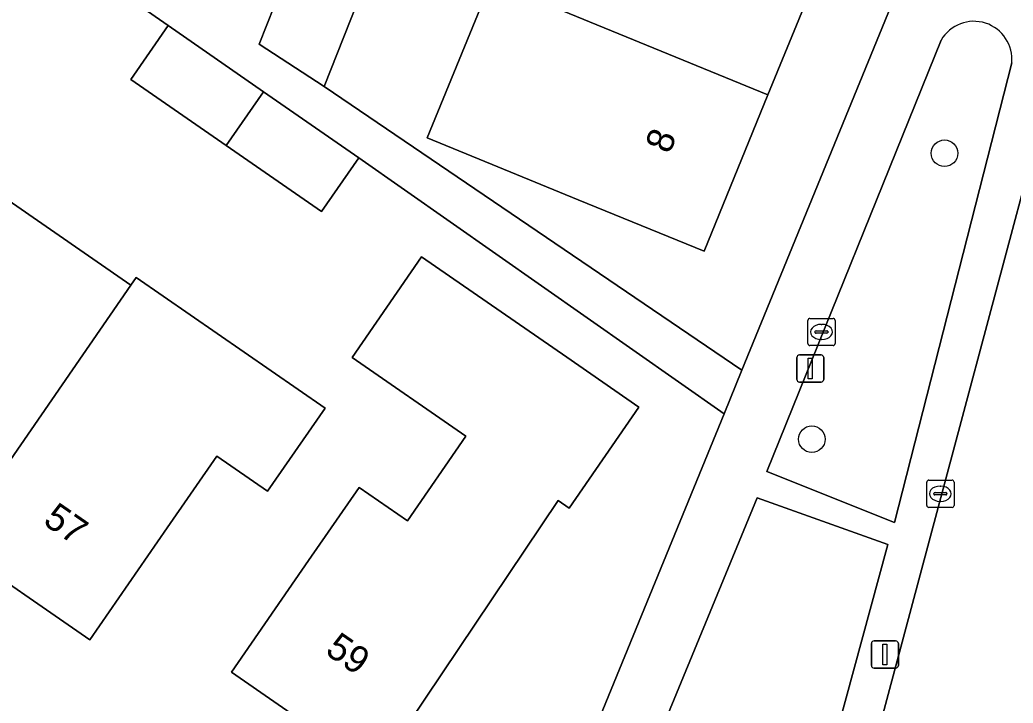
# Model space of a CAD drawing. Extents: x 162803 to 163818, y 381639 to 382475.
# Drawn here: x 163298.83 to 163335.38, y 381902.11 to 381927.23 of the extents above; entities that cross this region are included whole.
import ezdxf

# ---------------------------------------------------------------- set-up
doc = ezdxf.new("R2010")
doc.units = 0
for name, color, linetype in [('IMGEO_Boom', 7, 'Continuous'), ('IMGEO_Erf', 7, 'Continuous'), ('IMGEO_Groenvoorziening', 7, 'Continuous'), ('IMGEO_Kolk', 7, 'Continuous'), ('IMGEO_Lichtmast', 7, 'Continuous'), ('IMGEO_Pand', 7, 'Continuous'), ('IMGEO_Pand_nummerreeks', 7, 'Continuous'), ('IMGEO_Rijbaan_lokaal_open', 7, 'Continuous'), ('IMGEO_Voetpad_open', 7, 'Continuous')]:
    doc.layers.add(name, color=color, linetype=linetype)

msp = doc.modelspace()

# ---------------------------------------------------------------- linework, layer by layer
at = {"layer": 'IMGEO_Boom'}
for centre in [(163332.858, 381922.325), (163327.972, 381911.812)]:
    msp.add_circle(centre, 0.489, dxfattribs=at)
at = {"layer": 'IMGEO_Erf'}
for points in [[(163337.762, 381940.645), (163309.811, 381952.487), (163309.024, 381950.542), (163314.886, 381948.141), (163313.334, 381944.351), (163312.088, 381941.309), (163310.843, 381938.267), (163309.598, 381935.225), (163308.358, 381932.197), (163309.738, 381931.65), (163311.106, 381935.117), (163313.706, 381934.091), (163312.199, 381930.271), (163310.033, 381924.777), (163325.4, 381914.344), (163332.221, 381930.991), (163335.518, 381932.057)], [(163323.368, 381938.801), (163325.723, 381944.553), (163328.684, 381943.341), (163333.311, 381941.446), (163330.956, 381935.694), (163328.658, 381930.083), (163326.361, 381924.472), (163324.007, 381918.723), (163319.38, 381920.618), (163316.419, 381921.83), (163313.815, 381922.896), (163316.169, 381928.645), (163318.773, 381927.579), (163321.07, 381933.19)], [(163306.42, 381922.605), (163302.91, 381925.033), (163304.283, 381927.018), (163296.762, 381932.249), (163296.673, 381932.282), (163291.676, 381934.146), (163284.175, 381936.467), (163283.558, 381934.136), (163279.55, 381935.197), (163275.54, 381936.258), (163276.157, 381938.589), (163265.939, 381941.198), (163262.719, 381928.933), (163262.737, 381927.272), (163262.993, 381926.715), (163263.886, 381925.565), (163279.163, 381915.031), (163284.116, 381911.615), (163313.54, 381891.287), (163316.437, 381892.468), (163324.747, 381912.749), (163311.302, 381922.163), (163309.929, 381920.178)], [(163311.057, 381914.819), (163313.615, 381918.52), (163318.955, 381914.83), (163321.613, 381912.993), (163319.046, 381909.279), (163318.645, 381909.556), (163311.926, 381899.566), (163306.613, 381903.239), (163309.457, 381907.353), (163311.314, 381910.04), (163313.092, 381908.811), (163315.245, 381911.924)]]:
    msp.add_lwpolyline(points, close=True, dxfattribs=at)
msp.add_lwpolyline([(163295.64, 381927.812), (163292.797, 381923.7), (163291.24, 381921.447), (163296.05, 381918.122), (163296.477, 381917.827), (163298.397, 381920.603), (163302.92, 381917.476), (163303.116, 381917.759), (163310.061, 381912.957), (163307.945, 381909.897), (163306.077, 381911.189), (163304.25, 381908.546), (163301.406, 381904.433), (163296.331, 381907.941), (163291.38, 381911.364), (163286.305, 381914.872), (163289.794, 381919.919), (163287.322, 381921.628), (163284.851, 381923.335), (163281.365, 381918.292), (163276.283, 381921.805), (163271.323, 381925.235), (163266.238, 381928.75)], dxfattribs=at)
at = {"layer": 'IMGEO_Groenvoorziening'}
for points in [[(163332.732, 381926.487), (163326.319, 381910.623), (163331.019, 381908.748), (163335.33, 381925.646)], [(163330.776, 381907.94), (163325.963, 381909.657), (163320.28, 381895.893), (163318.976, 381892.714)], [(163325.799, 381889.715), (163326.399, 381891.882), (163330.776, 381907.94)]]:
    msp.add_lwpolyline(points, dxfattribs=at)
msp.add_arc((163333.938, 381925.779), 1.398, 354.5574, 149.568, dxfattribs=at)
at = {"layer": 'IMGEO_Kolk'}
for p, q in [((163327.904, 381916.254), (163328.756, 381916.254)), ((163327.829, 381915.328), (163327.829, 381916.18)), ((163328.317, 381916.034), (163328.342, 381916.034)), ((163328.83, 381916.18), (163328.83, 381915.328)), ((163328.088, 381915.748), (163328.088, 381915.76)), ((163328.526, 381915.711), (163328.128, 381915.711)), ((163328.131, 381915.797), (163328.529, 381915.797)), ((163328.572, 381915.76), (163328.572, 381915.748)), ((163328.756, 381915.254), (163327.904, 381915.254)), ((163328.34, 381915.474), (163328.315, 381915.474)), ((163332.205, 381909.379), (163332.205, 381910.231)), ((163332.28, 381910.305), (163333.132, 381910.305)), ((163332.693, 381910.085), (163332.718, 381910.085)), ((163333.206, 381910.231), (163333.206, 381909.379)), ((163332.464, 381909.799), (163332.464, 381909.811)), ((163332.902, 381909.762), (163332.504, 381909.762)), ((163332.507, 381909.848), (163332.905, 381909.848)), ((163332.948, 381909.811), (163332.948, 381909.799)), ((163332.716, 381909.525), (163332.691, 381909.525)), ((163333.132, 381909.305), (163332.28, 381909.305))]:
    msp.add_line(p, q, dxfattribs=at)
for points in [[(163327.904, 381916.254), (163328.756, 381916.254)], [(163327.829, 381915.328), (163327.829, 381916.18)], [(163328.83, 381916.18), (163328.83, 381915.328)], [(163328.756, 381915.254), (163327.904, 381915.254)], [(163332.205, 381909.379), (163332.205, 381910.231)], [(163332.28, 381910.305), (163333.132, 381910.305)], [(163333.206, 381910.231), (163333.206, 381909.379)], [(163333.132, 381909.305), (163332.28, 381909.305)]]:
    msp.add_lwpolyline(points, dxfattribs=at)
for centre, radius, start, end in [((163327.906, 381916.178), 0.0765, 91.552, 178.448), ((163327.906, 381916.178), 0.0765, 91.552, 178.448), ((163328.754, 381916.178), 0.0765, 1.552, 88.448), ((163328.754, 381916.178), 0.0765, 1.552, 88.448), ((163328.128, 381915.757), 0.0403, 85.8775, 175.7526), ((163328.125, 381915.747), 0.0366, 178.938, 274.7102), ((163328.529, 381915.754), 0.043, 264.8664, 352.4533), ((163328.533, 381915.759), 0.0386, 1.7309, 96.639), ((163327.906, 381915.33), 0.0765, 181.552, 268.448), ((163327.906, 381915.33), 0.0765, 181.552, 268.448), ((163328.754, 381915.33), 0.0765, 271.552, 358.448), ((163328.754, 381915.33), 0.0765, 271.552, 358.448), ((163332.282, 381910.229), 0.0765, 91.552, 178.448), ((163332.282, 381910.229), 0.0765, 91.552, 178.448), ((163333.13, 381910.229), 0.0765, 1.552, 88.448), ((163333.13, 381910.229), 0.0765, 1.552, 88.448), ((163332.504, 381909.808), 0.0403, 85.8775, 175.7526), ((163332.501, 381909.798), 0.0366, 178.938, 274.7102), ((163332.905, 381909.805), 0.043, 264.8664, 352.4533), ((163332.909, 381909.81), 0.0386, 1.7309, 96.639), ((163332.282, 381909.381), 0.0765, 181.552, 268.448), ((163332.282, 381909.381), 0.0765, 181.552, 268.448), ((163333.13, 381909.381), 0.0765, 271.552, 358.448), ((163333.13, 381909.381), 0.0765, 271.552, 358.448)]:
    msp.add_arc(centre, radius, start, end, dxfattribs=at)
for centre, major_axis, ratio, start_param, end_param in [((163328.316, 381915.754), (-0.387, 0.002), 0.722429, 4.712389, 7.853982), ((163328.341, 381915.754), (-0.39, 0.002), 0.717154, 1.570796, 4.712389), ((163332.692, 381909.805), (-0.387, 0.002), 0.722429, 4.712389, 7.853982), ((163332.717, 381909.805), (-0.39, 0.002), 0.717154, 1.570796, 4.712389)]:
    msp.add_ellipse(centre, major_axis=major_axis, ratio=ratio, start_param=start_param, end_param=end_param, dxfattribs=at)
at = {"layer": 'IMGEO_Lichtmast'}
for p, q in [((163327.422, 381914.01), (163327.422, 381914.81)), ((163327.422, 381914.81), (163327.422, 381914.01)), ((163327.522, 381914.91), (163328.312, 381914.91)), ((163328.312, 381914.91), (163327.522, 381914.91)), ((163328.412, 381914.81), (163328.412, 381914.01)), ((163328.412, 381914.01), (163328.412, 381914.81)), ((163328.312, 381913.91), (163327.522, 381913.91)), ((163327.522, 381913.91), (163328.312, 381913.91)), ((163330.168, 381903.494), (163330.168, 381904.294)), ((163330.168, 381904.294), (163330.168, 381903.494)), ((163330.268, 381904.394), (163331.058, 381904.394)), ((163331.058, 381904.394), (163330.268, 381904.394)), ((163331.158, 381904.294), (163331.158, 381903.494)), ((163331.158, 381903.494), (163331.158, 381904.294)), ((163331.058, 381903.394), (163330.268, 381903.394)), ((163330.268, 381903.394), (163331.058, 381903.394))]:
    msp.add_line(p, q, dxfattribs=at)
for points in [[(163327.842, 381914.785), (163327.992, 381914.785), (163327.992, 381914.035), (163327.842, 381914.035), (163327.842, 381914.785)], [(163330.588, 381904.269), (163330.738, 381904.269), (163330.738, 381903.519), (163330.588, 381903.519), (163330.588, 381904.269)]]:
    msp.add_lwpolyline(points, dxfattribs=at)
for centre, start, end in [((163327.522, 381914.81), 90, 180), ((163327.522, 381914.81), 90, 180), ((163328.312, 381914.81), 0, 90), ((163328.312, 381914.81), 360, 90), ((163327.522, 381914.01), 180, 270), ((163327.522, 381914.01), 180, 270), ((163328.312, 381914.01), 270, 0), ((163328.312, 381914.01), 270, 0), ((163330.268, 381904.294), 90, 180), ((163330.268, 381904.294), 90, 180), ((163331.058, 381904.294), 0, 90), ((163331.058, 381904.294), 360, 90), ((163330.268, 381903.494), 180, 270), ((163330.268, 381903.494), 180, 270), ((163331.058, 381903.494), 270, 0), ((163331.058, 381903.494), 270, 0)]:
    msp.add_arc(centre, 0.1, start, end, dxfattribs=at)
at = {"layer": 'IMGEO_Pand'}
for points in [[(163321.07, 381933.19), (163318.773, 381927.579), (163326.361, 381924.472), (163328.658, 381930.083)], [(163312.199, 381930.271), (163309.612, 381931.33), (163307.643, 381926.338), (163310.033, 381924.777)], [(163326.361, 381924.472), (163318.773, 381927.579), (163316.169, 381928.645), (163313.815, 381922.896), (163316.419, 381921.83), (163319.38, 381920.618), (163324.007, 381918.723)], [(163307.793, 381924.59), (163304.283, 381927.018), (163302.91, 381925.033), (163306.42, 381922.605)], [(163307.793, 381924.59), (163306.42, 381922.605), (163309.929, 381920.178), (163311.302, 381922.163)], [(163302.92, 381917.476), (163298.397, 381920.603), (163296.477, 381917.827), (163296.05, 381918.122), (163291.38, 381911.364), (163296.331, 381907.941)], [(163318.645, 381909.556), (163319.046, 381909.279), (163321.613, 381912.993), (163318.955, 381914.83), (163313.615, 381918.52), (163311.057, 381914.819), (163315.245, 381911.924), (163313.092, 381908.811), (163311.314, 381910.04), (163309.457, 381907.353), (163306.613, 381903.239), (163311.926, 381899.566)], [(163306.077, 381911.189), (163307.945, 381909.897), (163310.061, 381912.957), (163303.116, 381917.759), (163302.92, 381917.476), (163296.331, 381907.941), (163301.406, 381904.433), (163304.25, 381908.546)]]:
    msp.add_lwpolyline(points, close=True, dxfattribs=at)
at = {"layer": 'IMGEO_Rijbaan_lokaal_open'}
msp.add_lwpolyline([(163346.974, 381957.941), (163345.777, 381955.212), (163343.979, 381951.2), (163342.879, 381947.698), (163342.269, 381945.397), (163341.305, 381941.763), (163328.227, 381892.894), (163326.344, 381885.984), (163331.151, 381884.601), (163332.971, 381891.319), (163334.132, 381895.953), (163335.318, 381900.38), (163335.427, 381900.82), (163336.429, 381904.454), (163347.786, 381946.853)], dxfattribs=at)
at = {"layer": 'IMGEO_Voetpad_open'}
for points in [[(163347.42, 381960.503), (163345.145, 381961.444), (163340.821, 381951.498), (163340.262, 381950.209), (163338.117, 381942.001), (163337.762, 381940.645), (163335.518, 381932.057), (163332.221, 381930.991), (163325.4, 381914.344), (163324.747, 381912.749), (163316.437, 381892.468), (163312.179, 381886.77), (163312.585, 381885.073)], [(163326.012, 381884.905), (163326.344, 381885.984), (163328.227, 381892.894), (163341.305, 381941.763)], [(163335.33, 381925.646), (163331.019, 381908.748), (163326.319, 381910.623), (163332.732, 381926.487)], [(163318.976, 381892.714), (163320.28, 381895.893), (163325.963, 381909.657), (163330.776, 381907.94)], [(163330.776, 381907.94), (163326.399, 381891.882), (163325.799, 381889.715)]]:
    msp.add_lwpolyline(points, dxfattribs=at)
msp.add_lwpolyline([(163309.612, 381931.33), (163309.738, 381931.65), (163308.358, 381932.197), (163307.172, 381932.682), (163306.194, 381930.294), (163302.355, 381931.866), (163301.752, 381930.388), (163296.762, 381932.249), (163304.283, 381927.018), (163307.793, 381924.59), (163311.302, 381922.163), (163324.747, 381912.749), (163325.4, 381914.344), (163310.033, 381924.777), (163307.643, 381926.338)], close=True, dxfattribs=at)
msp.add_arc((163333.938, 381925.779), 1.398, 354.5574, 149.568, dxfattribs=at)

# ---------------------------------------------------------------- texts
at = {"layer": 'IMGEO_Pand_nummerreeks'}
for s, rotation, p in [('8', 67.7351, (163322.734, 381922.267)), ('57', 325.3475, (163299.642, 381908.716)), ('59', 325.3418, (163310.023, 381903.946))]:
    msp.add_text(s, height=1, rotation=rotation, dxfattribs=at).set_placement(p)

doc.saveas('drawing.dxf')
